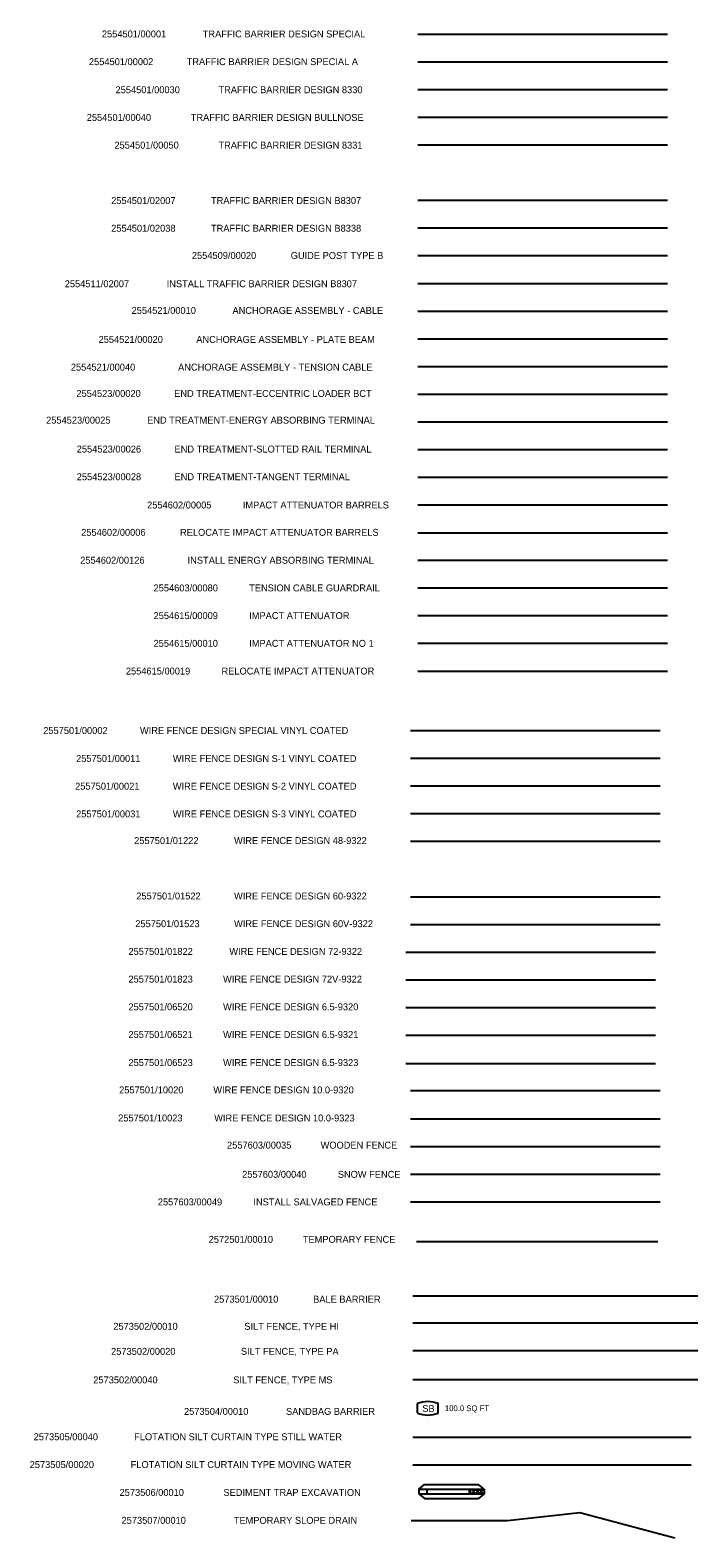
# Model space of a CAD drawing. Extents: x 2147712 to 2176316, y 2125036 to 2131746.
# Drawn here: x 2155047 to 2155770, y 2127870 to 2129503 of the extents above; entities that cross this region are included whole.
import ezdxf

# ---------------------------------------------------------------- set-up
doc = ezdxf.new("R2010")
doc.units = 0
for name, color, linetype in [('DETAIL TXT', 7, 'Continuous'), ('ERSN CTRL', 7, 'Continuous'), ('FENCE', 7, 'Continuous'), ('GDRL', 7, 'Continuous')]:
    doc.layers.add(name, color=color, linetype=linetype)

msp = doc.modelspace()

# ---------------------------------------------------------------- linework, layer by layer
at = {"layer": 'ERSN CTRL'}
for p, q in [((2155461.4, 2128132.2), (2155770.2, 2128132.2)), ((2155461.4, 2128102.9), (2155770.2, 2128102.9)), ((2155461.4, 2128073), (2155770.2, 2128073)), ((2155461.4, 2128041.4), (2155770.2, 2128041.4)), ((2155466.5, 2128010.4), (2155466.5, 2128015.4)), ((2155489.1, 2128010.4), (2155489.1, 2128015.4)), ((2155466.5, 2128005.4), (2155466.5, 2128010.4)), ((2155489.1, 2128005.4), (2155489.1, 2128010.4)), ((2155461.3, 2127979.2), (2155763, 2127979.2)), ((2155461.3, 2127949.1), (2155763, 2127949.1)), ((2155468.1, 2127922.8), (2155474, 2127927.8)), ((2155468.1, 2127922.8), (2155468.1, 2127917.8)), ((2155468.1, 2127922.8), (2155485.4, 2127922.8)), ((2155468.1, 2127917.8), (2155474.1, 2127912.8)), ((2155468.1, 2127917.8), (2155485.4, 2127917.8)), ((2155474, 2127927.8), (2155485.4, 2127927.8)), ((2155476.6, 2127922.8), (2155476.6, 2127917.8)), ((2155485.4, 2127927.8), (2155532.7, 2127927.8)), ((2155485.4, 2127922.8), (2155538.6, 2127922.8)), ((2155485.4, 2127917.8), (2155538.6, 2127917.8)), ((2155522.6, 2127922.8), (2155522.6, 2127917.8)), ((2155522.6, 2127919.5), (2155525.9, 2127922.8)), ((2155522.6, 2127921.1), (2155525.9, 2127917.8)), ((2155524.9, 2127922.8), (2155529.9, 2127917.8)), ((2155524.9, 2127917.8), (2155529.9, 2127922.8)), ((2155528.9, 2127922.8), (2155533.9, 2127917.8)), ((2155528.9, 2127917.8), (2155533.9, 2127922.8)), ((2155538.6, 2127917.8), (2155532.6, 2127912.8)), ((2155538.6, 2127922.8), (2155532.7, 2127927.8)), ((2155532.9, 2127922.8), (2155537.9, 2127917.8)), ((2155532.9, 2127917.8), (2155537.9, 2127922.8)), ((2155536.9, 2127922.8), (2155538.6, 2127921.1)), ((2155536.9, 2127917.8), (2155538.6, 2127919.5)), ((2155538.6, 2127922.8), (2155538.6, 2127917.8)), ((2155474.1, 2127912.8), (2155485.4, 2127912.8)), ((2155485.4, 2127912.8), (2155532.6, 2127912.8)), ((2155459.7, 2127888.7), (2155564, 2127888.7)), ((2155564, 2127888.7), (2155642.5, 2127897.6)), ((2155642.5, 2127897.6), (2155745.2, 2127870.1))]:
    msp.add_line(p, q, dxfattribs=at)
for centre, start, end in [((2155477.8, 2127988.2), 67.4378, 112.5622), ((2155477.8, 2128032.5), 247.4378, 292.5622)]:
    msp.add_arc(centre, 29.5, start, end, dxfattribs=at)
at = {"layer": 'FENCE'}
for p, q in [((2155459, 2128744.4), (2155729.5, 2128744.4)), ((2155459, 2128714.4), (2155729.5, 2128714.4)), ((2155459, 2128684.4), (2155729.5, 2128684.4)), ((2155459, 2128654.4), (2155729.5, 2128654.4)), ((2155459, 2128624.4), (2155729.5, 2128624.4)), ((2155459, 2128564.4), (2155729.5, 2128564.4)), ((2155459, 2128534.4), (2155729.5, 2128534.4)), ((2155454, 2128504.4), (2155724.4, 2128504.4)), ((2155454, 2128474.4), (2155724.4, 2128474.4)), ((2155454, 2128444.4), (2155724.4, 2128444.4)), ((2155454, 2128414.4), (2155724.4, 2128414.4)), ((2155454, 2128383.9), (2155724.4, 2128383.9)), ((2155459, 2128354.4), (2155729.5, 2128354.4)), ((2155459, 2128323.9), (2155729.5, 2128323.9)), ((2155459, 2128293.9), (2155729.5, 2128293.9)), ((2155459, 2128263.9), (2155729.5, 2128263.9)), ((2155459, 2128233.9), (2155729.5, 2128233.9)), ((2155465.6, 2128191.1), (2155727, 2128191.1))]:
    msp.add_line(p, q, dxfattribs=at)
at = {"layer": 'GDRL'}
for p, q in [((2155466.9, 2129498.6), (2155737.3, 2129498.6)), ((2155466.9, 2129468.6), (2155737.3, 2129468.6)), ((2155466.9, 2129438.6), (2155737.3, 2129438.6)), ((2155466.9, 2129408.6), (2155737.3, 2129408.6)), ((2155466.9, 2129378.6), (2155737.3, 2129378.6)), ((2155466.9, 2129318.6), (2155737.3, 2129318.6)), ((2155466.9, 2129288.6), (2155737.3, 2129288.6)), ((2155466.9, 2129258.6), (2155737.3, 2129258.6)), ((2155466.9, 2129228.6), (2155737.3, 2129228.6)), ((2155466.9, 2129198.6), (2155737.3, 2129198.6)), ((2155466.9, 2129168.6), (2155737.3, 2129168.6)), ((2155466.9, 2129138.6), (2155737.3, 2129138.6)), ((2155466.9, 2129108.6), (2155737.3, 2129108.6)), ((2155466.9, 2129078.6), (2155737.3, 2129078.6)), ((2155466.9, 2129048.6), (2155737.3, 2129048.6)), ((2155466.9, 2129018.6), (2155737.3, 2129018.6)), ((2155466.9, 2128988.6), (2155737.3, 2128988.6)), ((2155466.9, 2128958.6), (2155737.3, 2128958.6)), ((2155466.9, 2128928.8), (2155737.3, 2128928.8)), ((2155466.9, 2128898.8), (2155737.3, 2128898.8)), ((2155466.9, 2128868.8), (2155737.3, 2128868.8)), ((2155466.9, 2128838.8), (2155737.3, 2128838.8)), ((2155466.9, 2128808.8), (2155737.3, 2128808.8))]:
    msp.add_line(p, q, dxfattribs=at)

# ---------------------------------------------------------------- texts
at = {"layer": 'DETAIL TXT'}
for s, p in [('2554501/00001', (2155124.6, 2129494.9)), ('TRAFFIC BARRIER DESIGN SPECIAL', (2155233.9, 2129494.9)), ('2554501/00002', (2155110.6, 2129464.9)), ('TRAFFIC BARRIER DESIGN SPECIAL A', (2155216.5, 2129464.9)), ('2554501/00030', (2155139.4, 2129434.5)), ('TRAFFIC BARRIER DESIGN 8330', (2155250.9, 2129434.5)), ('2554501/00040', (2155108.2, 2129404.5)), ('TRAFFIC BARRIER DESIGN BULLNOSE', (2155220.9, 2129404.5)), ('2554501/00050', (2155138.2, 2129374.5)), ('TRAFFIC BARRIER DESIGN 8331', (2155250.9, 2129374.5)), ('2554501/02007', (2155134.7, 2129314.5)), ('TRAFFIC BARRIER DESIGN B8307', (2155242.8, 2129314.5)), ('2554501/02038', (2155134.7, 2129284.5)), ('TRAFFIC BARRIER DESIGN B8338', (2155242.8, 2129284.5)), ('2554509/00020', (2155222.1, 2129255)), ('GUIDE POST TYPE B', (2155329.2, 2129255)), ('2554511/02007', (2155084.4, 2129224.4)), ('INSTALL TRAFFIC BARRIER DESIGN B8307', (2155194.8, 2129224.4)), ('2554521/00010', (2155156.8, 2129195.5)), ('ANCHORAGE ASSEMBLY - CABLE', (2155266.1, 2129195.5)), ('2554521/00020', (2155121, 2129164.1)), ('ANCHORAGE ASSEMBLY - PLATE BEAM', (2155226.9, 2129164.1)), ('2554521/00040', (2155091, 2129134.1)), ('ANCHORAGE ASSEMBLY - TENSION CABLE', (2155207.2, 2129134.1)), ('2554523/00020', (2155097, 2129105.6)), ('END TREATMENT-ECCENTRIC LOADER BCT', (2155202.9, 2129105.6)), ('2554523/00025', (2155064.2, 2129076.7)), ('END TREATMENT-ENERGY ABSORBING TERMINAL', (2155173.6, 2129076.7)), ('2554523/00026', (2155097.4, 2129045.4)), ('END TREATMENT-SLOTTED RAIL TERMINAL', (2155203.3, 2129045.4)), ('2554523/00028', (2155097.4, 2129015.4)), ('END TREATMENT-TANGENT TERMINAL', (2155203.3, 2129015.4)), ('2554602/00005', (2155173.6, 2128984.8)), ('IMPACT ATTENUATOR BARRELS', (2155277.3, 2128984.8)), ('2554602/00006', (2155102.2, 2128955.2)), ('RELOCATE IMPACT ATTENUATOR BARRELS', (2155209.3, 2128955.2)), ('2554602/00126', (2155101.1, 2128925)), ('INSTALL ENERGY ABSORBING TERMINAL', (2155217.5, 2128925)), ('2554603/00080', (2155180.6, 2128895)), ('TENSION CABLE GUARDRAIL', (2155284.2, 2128895)), ('2554615/00009', (2155180.6, 2128865)), ('IMPACT ATTENUATOR', (2155284.2, 2128865)), ('2554615/00010', (2155180.6, 2128835)), ('IMPACT ATTENUATOR NO 1', (2155284.2, 2128835)), ('2554615/00019', (2155150.6, 2128805)), ('RELOCATE IMPACT ATTENUATOR', (2155254.2, 2128805)), ('2557501/00002', (2155061.1, 2128740.6)), ('WIRE FENCE DESIGN SPECIAL VINYL COATED', (2155165.9, 2128740.6)), ('2557501/00011', (2155096.7, 2128710.3)), ('WIRE FENCE DESIGN S-1 VINYL COATED', (2155201.5, 2128710.3)), ('2557501/00021', (2155095.6, 2128680.3)), ('WIRE FENCE DESIGN S-2 VINYL COATED', (2155201.5, 2128680.3)), ('2557501/00031', (2155096.7, 2128650.3)), ('WIRE FENCE DESIGN S-3 VINYL COATED', (2155201.5, 2128650.3)), ('2557501/01222', (2155159.6, 2128621.4)), ('WIRE FENCE DESIGN 48-9322', (2155267.8, 2128621.4)), ('2557501/01522', (2155161.9, 2128561.4)), ('WIRE FENCE DESIGN 60-9322', (2155267.8, 2128561.4)), ('2557501/01523', (2155160.8, 2128531.4)), ('WIRE FENCE DESIGN 60V-9322', (2155267.8, 2128531.4)), ('2557501/01822', (2155153.4, 2128501.4)), ('WIRE FENCE DESIGN 72-9322', (2155262.7, 2128501.4)), ('2557501/01823', (2155153.4, 2128471.4)), ('WIRE FENCE DESIGN 72V-9322', (2155255.9, 2128471.4)), ('2557501/06520', (2155153.4, 2128441.4)), ('WIRE FENCE DESIGN 6.5-9320', (2155255.9, 2128441.4)), ('2557501/06521', (2155153.4, 2128411.4)), ('WIRE FENCE DESIGN 6.5-9321', (2155255.9, 2128411.4)), ('2557501/06523', (2155153.4, 2128381)), ('WIRE FENCE DESIGN 6.5-9323', (2155255.9, 2128381)), ('2557501/10020', (2155143.3, 2128351.4)), ('WIRE FENCE DESIGN 10.0-9320', (2155245.3, 2128351.4)), ('2557501/10023', (2155142.3, 2128321)), ('WIRE FENCE DESIGN 10.0-9323', (2155246.3, 2128321)), ('2557603/00035', (2155260.2, 2128291.6)), ('WOODEN FENCE', (2155361.6, 2128291.6)), ('2557603/00040', (2155276.6, 2128260)), ('SNOW FENCE', (2155380.2, 2128260)), ('2557603/00049', (2155185.2, 2128230.1)), ('INSTALL SALVAGED FENCE', (2155288.8, 2128230.1)), ('2572501/00010', (2155240.3, 2128189.6)), ('TEMPORARY FENCE', (2155342.3, 2128189.6)), ('2573501/00010', (2155246.1, 2128124.8)), ('BALE BARRIER', (2155353.5, 2128124.8)), ('2573502/00010', (2155137, 2128095.4)), ('SILT FENCE, TYPE HI', (2155278.9, 2128095.4)), ('2573502/00020', (2155134.6, 2128068.3)), ('SILT FENCE, TYPE PA', (2155275.2, 2128068.3)), ('2573502/00040', (2155115.3, 2128037.4)), ('SILT FENCE, TYPE MS', (2155266.9, 2128037.4)), ('2573504/00010', (2155213.6, 2128003.3)), ('SANDBAG BARRIER', (2155324.1, 2128003.3)), ('2573505/00040', (2155050.7, 2127975.8)), ('FLOTATION SILT CURTAIN TYPE STILL WATER', (2155159.6, 2127975.8)), ('2573505/00020', (2155046.4, 2127945.7)), ('FLOTATION SILT CURTAIN TYPE MOVING WATER', (2155155.8, 2127945.7)), ('2573506/00010', (2155143.8, 2127915.5)), ('SEDIMENT TRAP EXCAVATION', (2155256.3, 2127915.5)), ('2573507/00010', (2155145.9, 2127885.3)), ('TEMPORARY SLOPE DRAIN', (2155267.5, 2127885.3))]:
    msp.add_text(s, height=7.5, dxfattribs=at).set_placement(p)
at = {"layer": 'ERSN CTRL'}
for s, height, p in [('SB', 7.5, (2155471.7, 2128006.4)), ('100.0 SQ FT', 6.25, (2155496.2, 2128007.3))]:
    msp.add_text(s, height=height, dxfattribs=at).set_placement(p)

doc.saveas('drawing.dxf')
